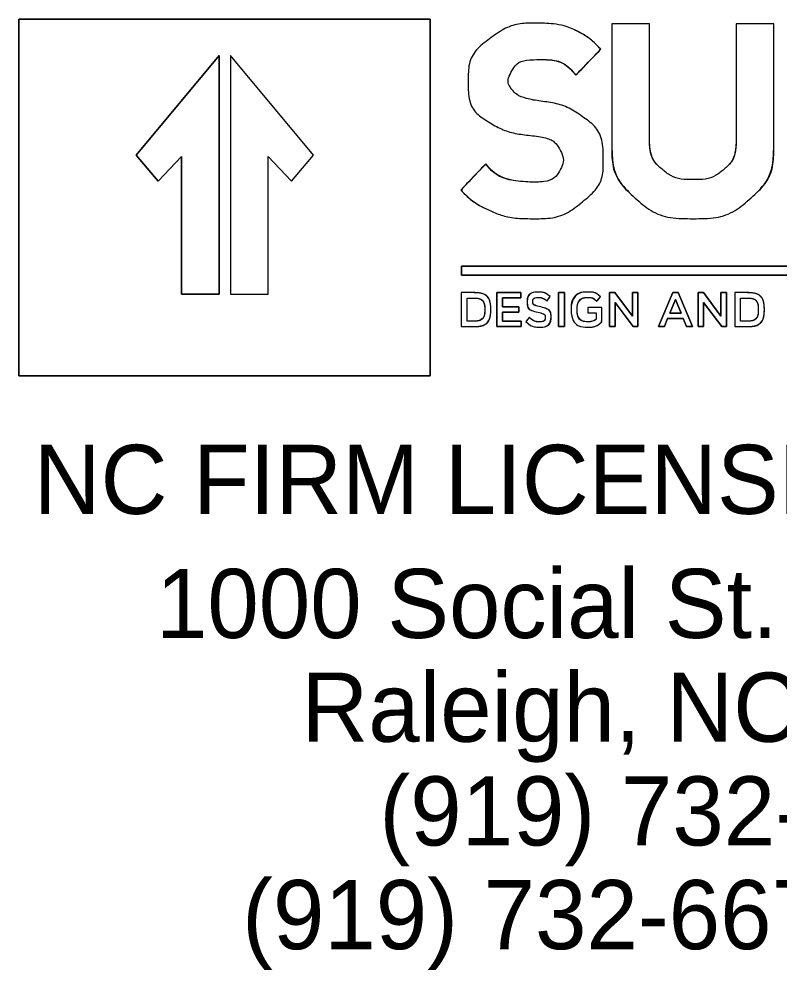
# Model space of a CAD drawing. Extents: x -0.71 to 3.09, y 0 to 1.8.
# Drawn here: x 2.6104 to 2.6952, y 1.2524 to 1.3583 of the extents above; entities that cross this region are included whole.
import ezdxf

# ---------------------------------------------------------------- set-up
doc = ezdxf.new("R2010")
doc.units = 0
doc.layers.add('P_NCDOT_Horizontal_Alignment_Tick_Small', color=7, linetype='Continuous')

msp = doc.modelspace()

# ---------------------------------------------------------------- linework, layer by layer
at = {"layer": 'P_NCDOT_Horizontal_Alignment_Tick_Small'}
for p, q in [((2.67246, 1.35204), (2.67524, 1.35495)), ((2.66243, 1.34217), (2.65964, 1.33926)), ((2.66925, 1.32691), (2.66959, 1.32741)), ((2.6748, 1.32688), (2.67521, 1.32738)), ((2.66703, 1.32679), (2.66703, 1.32678)), ((2.66767, 1.32684), (2.66767, 1.32685)), ((2.66232, 1.32594), (2.66232, 1.32593)), ((2.66299, 1.32594), (2.66299, 1.32595)), ((2.67194, 1.32594), (2.67194, 1.32593)), ((2.67261, 1.32594), (2.67261, 1.32595)), ((2.69279, 1.32594), (2.69279, 1.32593)), ((2.69346, 1.32594), (2.69346, 1.32595)), ((2.66727, 1.32507), (2.66689, 1.3246)), ((2.66906, 1.32507), (2.66906, 1.32506)), ((2.6697, 1.32512), (2.6697, 1.32513))]:
    msp.add_line(p, q, dxfattribs=at)
for points in [[(2.65624, 1.35831), (2.61043, 1.35831), (2.61043, 1.31856), (2.65624, 1.31856), (2.65624, 1.35831)], [(2.68066, 1.34522), (2.68066, 1.35777), (2.67647, 1.35777), (2.67647, 1.34406)], [(2.69451, 1.34406), (2.69451, 1.35777), (2.69032, 1.35777), (2.69032, 1.34522)], [(2.63272, 1.35424), (2.63272, 1.32766), (2.62853, 1.32766), (2.62853, 1.343), (2.62594, 1.34025), (2.6235, 1.34316), (2.63272, 1.35424)], [(2.6235, 1.34316), (2.62594, 1.34025), (2.62853, 1.343), (2.62853, 1.32766), (2.63272, 1.32766), (2.63272, 1.35424), (2.6235, 1.34316)], [(2.63401, 1.35424), (2.63401, 1.32766), (2.63819, 1.32766), (2.63819, 1.343), (2.64079, 1.34025), (2.64322, 1.34316), (2.63401, 1.35424)], [(2.76119, 1.32977), (2.65972, 1.32977), (2.65972, 1.33077), (2.76119, 1.33077), (2.76119, 1.32977)], [(2.76119, 1.33077), (2.65972, 1.33077), (2.65972, 1.32977), (2.76119, 1.32977), (2.76119, 1.33077)], [(2.66106, 1.32783), (2.6597, 1.32783), (2.6597, 1.32405), (2.66106, 1.32405)], [(2.66365, 1.32783), (2.66635, 1.32783), (2.66635, 1.32724), (2.66429, 1.32724), (2.66429, 1.32625), (2.66611, 1.32625), (2.66611, 1.32566), (2.66429, 1.32566), (2.66429, 1.32464), (2.66637, 1.32464), (2.66637, 1.32405), (2.66365, 1.32405), (2.66365, 1.32783)], [(2.66365, 1.32405), (2.66637, 1.32405), (2.66637, 1.32464), (2.66429, 1.32464), (2.66429, 1.32566), (2.66611, 1.32566), (2.66611, 1.32625), (2.66429, 1.32625), (2.66429, 1.32724), (2.66635, 1.32724), (2.66635, 1.32783), (2.66365, 1.32783), (2.66365, 1.32405)], [(2.67054, 1.32783), (2.67118, 1.32783), (2.67118, 1.32405), (2.67054, 1.32405), (2.67054, 1.32783)], [(2.67054, 1.32405), (2.67118, 1.32405), (2.67118, 1.32783), (2.67054, 1.32783), (2.67054, 1.32405)], [(2.67622, 1.32783), (2.67681, 1.32783), (2.67876, 1.32521), (2.67876, 1.32783), (2.67938, 1.32783), (2.67938, 1.32405), (2.67885, 1.32405), (2.67684, 1.32674), (2.67684, 1.32405), (2.67622, 1.32405), (2.67622, 1.32783)], [(2.67622, 1.32405), (2.67684, 1.32405), (2.67684, 1.32674), (2.67885, 1.32405), (2.67938, 1.32405), (2.67938, 1.32783), (2.67876, 1.32783), (2.67876, 1.32521), (2.67681, 1.32783), (2.67622, 1.32783), (2.67622, 1.32405)], [(2.68326, 1.32786), (2.68386, 1.32786), (2.68545, 1.32405), (2.68478, 1.32405), (2.68441, 1.32496), (2.68269, 1.32496), (2.68232, 1.32405), (2.68167, 1.32405), (2.68326, 1.32786)], [(2.68167, 1.32405), (2.68232, 1.32405), (2.68269, 1.32496), (2.68441, 1.32496), (2.68478, 1.32405), (2.68545, 1.32405), (2.68386, 1.32786), (2.68326, 1.32786), (2.68167, 1.32405)], [(2.68608, 1.32783), (2.68667, 1.32783), (2.68861, 1.32521), (2.68861, 1.32783), (2.68924, 1.32783), (2.68924, 1.32405), (2.68871, 1.32405), (2.6867, 1.32674), (2.6867, 1.32405), (2.68608, 1.32405), (2.68608, 1.32783)], [(2.68608, 1.32405), (2.6867, 1.32405), (2.6867, 1.32674), (2.68871, 1.32405), (2.68924, 1.32405), (2.68924, 1.32783), (2.68861, 1.32783), (2.68861, 1.32521), (2.68667, 1.32783), (2.68608, 1.32783), (2.68608, 1.32405)], [(2.69153, 1.32783), (2.69018, 1.32783), (2.69018, 1.32405), (2.69153, 1.32405)], [(2.66106, 1.32465), (2.66034, 1.32465), (2.66034, 1.32723), (2.66106, 1.32723)], [(2.68418, 1.32555), (2.68355, 1.32706), (2.68293, 1.32555), (2.68418, 1.32555)], [(2.68293, 1.32555), (2.68355, 1.32706), (2.68418, 1.32555), (2.68293, 1.32555)], [(2.69153, 1.32465), (2.69081, 1.32465), (2.69081, 1.32723), (2.69153, 1.32723)], [(2.67534, 1.32457), (2.67534, 1.32616), (2.67379, 1.32616), (2.67379, 1.32558), (2.67472, 1.32558), (2.67472, 1.32487)]]:
    msp.add_lwpolyline(points, dxfattribs=at)
for points in [[(2.61043, 1.35831), (2.65624, 1.35831), (2.65624, 1.31856), (2.61043, 1.31856)], [(2.63401, 1.35424), (2.63401, 1.32766), (2.63819, 1.32766), (2.63819, 1.343), (2.64079, 1.34025), (2.64322, 1.34316)]]:
    msp.add_lwpolyline(points, close=True, dxfattribs=at)
for points, degree in [([(2.67225, 1.35713), (2.67331, 1.35664), (2.67431, 1.35592), (2.67524, 1.35495), (2.67524, 1.35495), (2.67246, 1.35204), (2.67246, 1.35204), (2.67153, 1.35321), (2.67023, 1.35379), (2.66855, 1.35379), (2.66688, 1.35379), (2.66581, 1.35338), (2.66535, 1.35255), (2.66489, 1.35173), (2.66489, 1.35103), (2.66535, 1.35045), (2.66581, 1.34987), (2.66688, 1.34943), (2.66855, 1.34914), (2.67032, 1.34895), (2.67192, 1.34834), (2.67336, 1.34732), (2.6748, 1.34631), (2.67552, 1.34469), (2.67552, 1.34246), (2.67552, 1.34071), (2.67475, 1.33921), (2.67321, 1.33796), (2.67168, 1.3367), (2.66989, 1.33607), (2.66784, 1.33607), (2.6659, 1.33607), (2.66428, 1.33636), (2.66298, 1.33694), (2.66168, 1.33752), (2.66057, 1.33829), (2.65964, 1.33926), (2.65964, 1.33926), (2.66243, 1.34217), (2.66243, 1.34217), (2.66335, 1.34101), (2.66493, 1.34033), (2.66716, 1.34013), (2.66902, 1.34013), (2.67018, 1.34055), (2.67064, 1.34137), (2.6711, 1.34219), (2.6711, 1.34301), (2.67064, 1.34384), (2.67018, 1.34466), (2.66902, 1.34517), (2.66716, 1.34536), (2.66549, 1.34556), (2.66396, 1.34609), (2.66256, 1.34696), (2.66117, 1.34783), (2.66047, 1.34933), (2.66047, 1.35146), (2.66047, 1.35339), (2.66127, 1.35494), (2.66285, 1.3561), (2.66443, 1.35727), (2.66606, 1.35785), (2.66773, 1.35785), (2.66967, 1.35785), (2.67118, 1.35761), (2.67225, 1.35713)], 3), ([(2.67225, 1.35713), (2.67118, 1.35761), (2.66967, 1.35785), (2.66773, 1.35785), (2.66606, 1.35785), (2.66443, 1.35727), (2.66285, 1.3561), (2.66127, 1.35494), (2.66047, 1.35339), (2.66047, 1.35146), (2.66047, 1.34933), (2.66117, 1.34783), (2.66256, 1.34696), (2.66396, 1.34609), (2.66549, 1.34556), (2.66716, 1.34536), (2.66902, 1.34517), (2.67018, 1.34466), (2.67064, 1.34384), (2.6711, 1.34301), (2.6711, 1.34219), (2.67064, 1.34137), (2.67018, 1.34055), (2.66902, 1.34013), (2.66716, 1.34013), (2.66493, 1.34033), (2.66335, 1.34101), (2.66243, 1.34217)], 3), ([(2.67524, 1.35495), (2.67431, 1.35592), (2.67331, 1.35664), (2.67225, 1.35713)], 2), ([(2.68066, 1.35777), (2.68066, 1.35777), (2.68066, 1.34522), (2.68066, 1.34522), (2.68066, 1.34357), (2.68113, 1.34236), (2.68206, 1.34159), (2.68299, 1.34081), (2.68416, 1.34042), (2.68555, 1.34042), (2.68694, 1.34042), (2.68805, 1.34081), (2.68898, 1.34159), (2.68991, 1.34236), (2.69032, 1.34357), (2.69032, 1.34522), (2.69032, 1.34522), (2.69032, 1.35777), (2.69032, 1.35777), (2.69032, 1.35777), (2.69451, 1.35777), (2.69451, 1.35777), (2.69451, 1.35777), (2.69451, 1.34406), (2.69451, 1.34406), (2.69451, 1.34183), (2.6937, 1.33994), (2.69198, 1.33839), (2.69026, 1.33684), (2.68813, 1.33607), (2.68553, 1.33607), (2.68293, 1.33607), (2.68077, 1.33684), (2.67905, 1.33839), (2.67733, 1.33994), (2.67647, 1.34183), (2.67647, 1.34406), (2.67647, 1.34406), (2.67647, 1.35777), (2.67647, 1.35777), (2.67647, 1.35777), (2.68066, 1.35777), (2.68066, 1.35777)], 3), ([(2.65964, 1.33926), (2.66057, 1.33829), (2.66168, 1.33752), (2.66298, 1.33694), (2.66428, 1.33636), (2.6659, 1.33607), (2.66784, 1.33607), (2.66989, 1.33607), (2.67168, 1.3367), (2.67321, 1.33796), (2.67475, 1.33921), (2.67552, 1.34071), (2.67552, 1.34246), (2.67552, 1.34469), (2.6748, 1.34631), (2.67336, 1.34732), (2.67192, 1.34834), (2.67032, 1.34895), (2.66855, 1.34914), (2.66688, 1.34943), (2.66581, 1.34987), (2.66535, 1.35045), (2.66489, 1.35103), (2.66489, 1.35173), (2.66535, 1.35255), (2.66581, 1.35338), (2.66688, 1.35379), (2.66855, 1.35379), (2.67023, 1.35379), (2.67153, 1.35321), (2.67246, 1.35204)], 3), ([(2.69032, 1.34522), (2.69032, 1.34357), (2.68991, 1.34236), (2.68898, 1.34159), (2.68805, 1.34081), (2.68694, 1.34042), (2.68555, 1.34042), (2.68416, 1.34042), (2.68299, 1.34081), (2.68206, 1.34159), (2.68113, 1.34236), (2.68066, 1.34357), (2.68066, 1.34522)], 3), ([(2.67647, 1.34406), (2.67647, 1.34183), (2.67733, 1.33994), (2.67905, 1.33839), (2.68077, 1.33684), (2.68293, 1.33607), (2.68553, 1.33607), (2.68813, 1.33607), (2.69026, 1.33684), (2.69198, 1.33839), (2.6937, 1.33994), (2.69451, 1.34183), (2.69451, 1.34406)], 3), ([(2.6597, 1.32783), (2.6597, 1.32783), (2.66106, 1.32783), (2.66106, 1.32783), (2.6622, 1.32783), (2.66299, 1.32702), (2.66299, 1.32595), (2.66299, 1.32595), (2.66299, 1.32594), (2.66299, 1.32594), (2.66299, 1.32487), (2.6622, 1.32405), (2.66106, 1.32405), (2.66106, 1.32405), (2.6597, 1.32405), (2.6597, 1.32405), (2.6597, 1.32405), (2.6597, 1.32783), (2.6597, 1.32783)], 3), ([(2.66299, 1.32595), (2.66299, 1.32702), (2.6622, 1.32783), (2.66106, 1.32783)], 2), ([(2.66689, 1.3246), (2.66689, 1.3246), (2.66727, 1.32507), (2.66727, 1.32507), (2.66762, 1.32476), (2.66797, 1.32458), (2.66842, 1.32458), (2.66881, 1.32458), (2.66906, 1.32478), (2.66906, 1.32506), (2.66906, 1.32506), (2.66906, 1.32507), (2.66906, 1.32507), (2.66906, 1.32534), (2.66892, 1.32548), (2.66824, 1.32565), (2.66747, 1.32584), (2.66703, 1.32608), (2.66703, 1.32678), (2.66703, 1.32678), (2.66703, 1.32679), (2.66703, 1.32679), (2.66703, 1.32744), (2.66755, 1.32789), (2.66827, 1.32789), (2.6688, 1.32789), (2.66922, 1.32772), (2.66959, 1.32741), (2.66959, 1.32741), (2.66925, 1.32691), (2.66925, 1.32691), (2.66892, 1.32716), (2.66859, 1.3273), (2.66826, 1.3273), (2.66789, 1.3273), (2.66767, 1.3271), (2.66767, 1.32685), (2.66767, 1.32685), (2.66767, 1.32684), (2.66767, 1.32684), (2.66767, 1.32655), (2.66784, 1.32642), (2.66854, 1.32624), (2.66931, 1.32605), (2.6697, 1.32576), (2.6697, 1.32513), (2.6697, 1.32513), (2.6697, 1.32512), (2.6697, 1.32512), (2.6697, 1.32441), (2.66917, 1.32399), (2.6684, 1.32399), (2.66785, 1.32399), (2.66732, 1.32419), (2.66689, 1.3246)], 3), ([(2.66959, 1.32741), (2.66922, 1.32772), (2.6688, 1.32789), (2.66827, 1.32789), (2.66755, 1.32789), (2.66703, 1.32744), (2.66703, 1.32679)], 3), ([(2.66767, 1.32685), (2.66767, 1.3271), (2.66789, 1.3273), (2.66826, 1.3273), (2.66859, 1.3273), (2.66892, 1.32716), (2.66925, 1.32691)], 3), ([(2.67194, 1.32593), (2.67194, 1.32593), (2.67194, 1.32594), (2.67194, 1.32594), (2.67194, 1.327), (2.67271, 1.3279), (2.67381, 1.3279), (2.67444, 1.3279), (2.67483, 1.32771), (2.67521, 1.32738), (2.67521, 1.32738), (2.6748, 1.32688), (2.6748, 1.32688), (2.67452, 1.32713), (2.67425, 1.32729), (2.67378, 1.32729), (2.67311, 1.32729), (2.67261, 1.32668), (2.67261, 1.32595), (2.67261, 1.32595), (2.67261, 1.32594), (2.67261, 1.32594), (2.67261, 1.32516), (2.6731, 1.32459), (2.67384, 1.32459), (2.67418, 1.32459), (2.67449, 1.3247), (2.67472, 1.32487), (2.67472, 1.32487), (2.67472, 1.32558), (2.67472, 1.32558), (2.67472, 1.32558), (2.67379, 1.32558), (2.67379, 1.32558), (2.67379, 1.32558), (2.67379, 1.32616), (2.67379, 1.32616), (2.67379, 1.32616), (2.67534, 1.32616), (2.67534, 1.32616), (2.67534, 1.32616), (2.67534, 1.32457), (2.67534, 1.32457), (2.67498, 1.32425), (2.67446, 1.32398), (2.67382, 1.32398), (2.67268, 1.32398), (2.67194, 1.32482), (2.67194, 1.32593)], 3), ([(2.67521, 1.32738), (2.67483, 1.32771), (2.67444, 1.3279), (2.67381, 1.3279), (2.67271, 1.3279), (2.67194, 1.327), (2.67194, 1.32594)], 3), ([(2.69018, 1.32783), (2.69018, 1.32783), (2.69153, 1.32783), (2.69153, 1.32783), (2.69267, 1.32783), (2.69346, 1.32702), (2.69346, 1.32595), (2.69346, 1.32595), (2.69346, 1.32594), (2.69346, 1.32594), (2.69346, 1.32487), (2.69267, 1.32405), (2.69153, 1.32405), (2.69153, 1.32405), (2.69018, 1.32405), (2.69018, 1.32405), (2.69018, 1.32405), (2.69018, 1.32783), (2.69018, 1.32783)], 3), ([(2.69346, 1.32595), (2.69346, 1.32702), (2.69267, 1.32783), (2.69153, 1.32783)], 2), ([(2.66034, 1.32723), (2.66034, 1.32723), (2.66034, 1.32465), (2.66034, 1.32465), (2.66034, 1.32465), (2.66106, 1.32465), (2.66106, 1.32465), (2.66182, 1.32465), (2.66232, 1.32519), (2.66232, 1.32593), (2.66232, 1.32593), (2.66232, 1.32594), (2.66232, 1.32594), (2.66232, 1.32668), (2.66182, 1.32723), (2.66106, 1.32723), (2.66106, 1.32723), (2.66034, 1.32723), (2.66034, 1.32723)], 3), ([(2.66106, 1.32723), (2.66182, 1.32723), (2.66232, 1.32668), (2.66232, 1.32594)], 2), ([(2.66703, 1.32678), (2.66703, 1.32608), (2.66747, 1.32584), (2.66824, 1.32565), (2.66892, 1.32548), (2.66906, 1.32534), (2.66906, 1.32507)], 3), ([(2.6697, 1.32513), (2.6697, 1.32576), (2.66931, 1.32605), (2.66854, 1.32624), (2.66784, 1.32642), (2.66767, 1.32655), (2.66767, 1.32684)], 3), ([(2.67261, 1.32595), (2.67261, 1.32668), (2.67311, 1.32729), (2.67378, 1.32729), (2.67425, 1.32729), (2.67452, 1.32713), (2.6748, 1.32688)], 3), ([(2.69081, 1.32723), (2.69081, 1.32723), (2.69081, 1.32465), (2.69081, 1.32465), (2.69081, 1.32465), (2.69153, 1.32465), (2.69153, 1.32465), (2.69229, 1.32465), (2.69279, 1.32519), (2.69279, 1.32593), (2.69279, 1.32593), (2.69279, 1.32594), (2.69279, 1.32594), (2.69279, 1.32668), (2.69229, 1.32723), (2.69153, 1.32723), (2.69153, 1.32723), (2.69081, 1.32723), (2.69081, 1.32723)], 3), ([(2.69153, 1.32723), (2.69229, 1.32723), (2.69279, 1.32668), (2.69279, 1.32594)], 2), ([(2.66106, 1.32405), (2.6622, 1.32405), (2.66299, 1.32487), (2.66299, 1.32594)], 2), ([(2.66232, 1.32593), (2.66232, 1.32519), (2.66182, 1.32465), (2.66106, 1.32465)], 2), ([(2.67194, 1.32593), (2.67194, 1.32482), (2.67268, 1.32398), (2.67382, 1.32398), (2.67446, 1.32398), (2.67498, 1.32425), (2.67534, 1.32457)], 3), ([(2.67472, 1.32487), (2.67449, 1.3247), (2.67418, 1.32459), (2.67384, 1.32459), (2.6731, 1.32459), (2.67261, 1.32516), (2.67261, 1.32594)], 3), ([(2.69153, 1.32405), (2.69267, 1.32405), (2.69346, 1.32487), (2.69346, 1.32594)], 2), ([(2.69279, 1.32593), (2.69279, 1.32519), (2.69229, 1.32465), (2.69153, 1.32465)], 2), ([(2.66689, 1.3246), (2.66732, 1.32419), (2.66785, 1.32399), (2.6684, 1.32399), (2.66917, 1.32399), (2.6697, 1.32441), (2.6697, 1.32512)], 3), ([(2.66906, 1.32506), (2.66906, 1.32478), (2.66881, 1.32458), (2.66842, 1.32458), (2.66797, 1.32458), (2.66762, 1.32476), (2.66727, 1.32507)], 3)]:
    msp.add_open_spline(points, degree=degree, dxfattribs=at)

# ---------------------------------------------------------------- texts
for s, p in [('NC FIRM LICENSE No: C-5176', (2.61209, 1.30318)), ('1000 Social St. Suite 800.', (2.62569, 1.28936)), ('Raleigh, NC 27609', (2.6419, 1.2778)), ('(919) 732-3883', (2.65058, 1.26625)), ('(919) 732-6676 (FAX)', (2.63529, 1.2547))]:
    msp.add_text(s, height=0.0077015, rotation=360, dxfattribs=at).set_placement(p)

doc.saveas('drawing.dxf')
